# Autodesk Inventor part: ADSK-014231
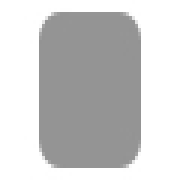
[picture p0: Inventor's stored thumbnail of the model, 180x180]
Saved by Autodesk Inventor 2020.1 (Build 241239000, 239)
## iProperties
Created: 2019-01
Part Number: ADSK-014231
Material: Stahl, weich
Document SubType Name: Modeling
Designer: lutzd
Language: de-DE
Size Designation: 5 x 39,384472 x 39,384472
Categories: <MemberInstance><Categories><Category DisplayName="Sonstige Bauteile" InternalName="5aa15e00-363f-49f2-933f-16f664388e3f" Mnemonic="OTHER"><Category DisplayName
Mass: 60.0398 g
Surface Area: 38.0412 cm^2
Volume: 7.64838 cm^3
Density: 7.85 g/cm^3
Appearance: Halbpoliert
Dimensions: 39,4x39,4x5 mm
Mass: 0,06 kg
DocNumber: ADSK-014231
Folder: 01 - Themengebiete\Simplification\01 - Packaging machine\ADSK-014200\Frame\
VDS_Category: 3D Komponenten
VDS_NumSchm: Autodesk
IsCustomPart: 1
Title: Endcap
Author: lutzd
Revision Number: -
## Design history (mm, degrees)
sketch "Sketch1"
  geometry: L1 (0, 20.175)-(0, -21.446); L2 (-20.203, 0)-(20.169, 0); L3 (-19.692, 19.692)-(19.692, 19.692); L4 (19.692, 19.692)-(19.692, -19.692); L5 (19.692, -19.692)-(-19.692, -19.692); L6 (-19.692, -19.692)-(-19.692, 19.692); 1 further point
  constraints: 12 end point, 2 horizontal, 2 parallel, 2 point on line, 1 perpendicular, 1 vertical
  dimensions: "d0" = 39.38447 distance between parallel lines of L5 L3 (= height); "d1" = 19.69224 distance between parallel lines of L2 L3 (= 0.5 x height); "d2" = 39.38447 distance between parallel lines of L6 L4 (= width); "d3" = 19.69224 distance between parallel lines of L6 L1 (= 0.5 x width)
extrude "Extrusion1" new body sketch "Sketch1" distance "d4" = 5 (= thickness); taper "d5" = 0 deg
fillet "Fillet1" dims "d6" = 5 (= fillet), "d7" = 0, "fillet" = 5 [user parameter; used in 1 equation term]
chamfer "Chamfer1" distance "d8" = 0 (computed from chamfer); stored, may be unused: second distance "d9" = 2, angle "d10" = 45 deg; dims "d11" = 0, "chamfer" = 0 [user parameter; used in 1 equation term]
body "Solid1"
other parameters: "thickness" = 5 [user parameter; used in 1 equation term], "width" = 39.38447 [user parameter; used in 2 equation terms], "height" = 39.38447 [user parameter; used in 2 equation terms]
